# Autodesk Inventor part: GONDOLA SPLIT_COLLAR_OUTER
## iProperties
Shininess: 64.0
Length Units: 11272
Angle Units: 11279
Time Units: 11290
Mass Units: 11286
Length Display Precision: 3
Angle Display Precision: 2
Compacted: True
Part Number: GONDOLA SPLIT_COLLAR_OUTER
Document SubType Name: Modeling
Created: 2004-08
Designer: John Blackburn
Manufacturer: Standard
Standards Organization: Custom
Material: Delrin, Black
Density: 0.0
Volumn: 0.0
Area: 0.0
PropertySet Name: Model Information
Control State: 0
Master: False
Checked Out: False
Author: John Blackburn
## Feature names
1. Base1
2. ExtrusionBlind1
3. AM_HOLE_SI0030_1 [Hole]
